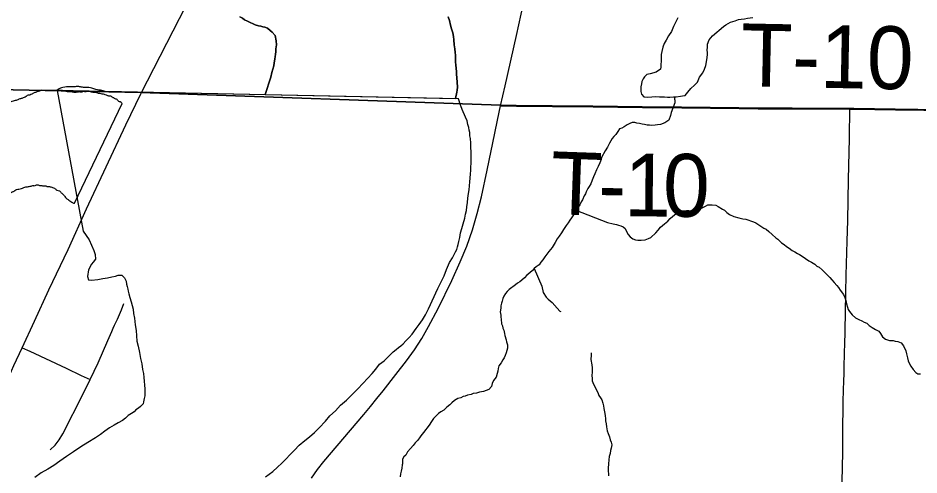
# Model space of a CAD drawing. Extents: x -483 to 680, y 0 to 440.
# Drawn here: x 111.22 to 151.99, y 110.14 to 130.81 of the extents above; entities that cross this region are included whole.
import ezdxf

# ---------------------------------------------------------------- set-up
doc = ezdxf.new("R2010")
doc.units = 0
for name, color, linetype in [('GM_X_County_Road', 7, 'Continuous'), ('GM_X_Major_River', 7, 'Continuous'), ('GM_X_Minor_Lake', 7, 'Continuous'), ('GM_X_Minor_River', 7, 'Continuous'), ('GM_X_State_Route', 7, 'Continuous'), ('GM_X_Township_Road', 7, 'Continuous'), ('GM_X_Township_Road_Text', 7, 'Continuous'), ('SH_Cut_Line', 7, 'Continuous')]:
    doc.layers.add(name, color=color, linetype=linetype)

msp = doc.modelspace()

# ---------------------------------------------------------------- linework, layer by layer
at = {"layer": 'GM_X_County_Road'}
for points in [[(133.061, 126.847), (133.259, 127.748), (133.774, 130.022), (134.2, 131.965)], [(124.501, 109.998), (124.772, 110.381), (125.061, 110.748), (125.664, 111.46), (126.869, 112.882), (127.164, 113.239), (127.456, 113.595), (127.746, 113.953), (128.32, 114.683), (128.794, 115.298), (129.156, 115.8), (129.491, 116.32), (129.802, 116.854), (130.234, 117.678), (130.851, 118.932), (131.235, 119.779), (131.524, 120.498), (131.78, 121.229), (132, 121.972), (132.191, 122.723), (132.454, 123.936), (132.804, 125.609), (132.925, 126.185), (133.061, 126.847)]]:
    msp.add_lwpolyline(points, dxfattribs=at)
at = {"layer": 'GM_X_Major_River'}
for p, q in [((113.154, 127.538), (112.286, 127.555)), ((131.149, 127.156), (112.985, 127.541)), ((122.408, 127.353), (131.016, 127.178)), ((113.77, 122.438), (115.939, 126.95))]:
    msp.add_line(p, q, dxfattribs=at)
for points in [[(121.264, 130.869), (121.376, 130.808), (121.469, 130.729), (121.6, 130.667), (121.732, 130.606), (121.863, 130.544), (121.957, 130.503), (122.108, 130.46), (122.202, 130.438), (122.297, 130.416), (122.391, 130.394), (122.504, 130.352), (122.634, 130.253), (122.727, 130.173), (122.855, 130.017), (122.905, 129.787), (122.918, 129.596), (122.893, 129.426), (122.889, 129.293), (122.866, 129.161), (122.863, 129.066), (122.84, 128.952), (122.816, 128.782), (122.792, 128.649), (122.749, 128.499), (122.706, 128.348), (122.662, 128.14), (122.408, 127.353)], [(122.408, 127.353), (122.662, 128.14), (122.706, 128.348), (122.749, 128.499), (122.792, 128.649), (122.816, 128.782), (122.84, 128.952), (122.863, 129.066), (122.866, 129.161), (122.889, 129.293), (122.893, 129.426), (122.918, 129.596), (122.905, 129.787), (122.855, 130.017), (122.727, 130.173), (122.634, 130.253), (122.504, 130.352), (122.391, 130.394), (122.297, 130.416), (122.202, 130.438), (122.108, 130.46), (121.957, 130.503), (121.863, 130.544), (121.732, 130.606), (121.6, 130.667), (121.469, 130.729), (121.376, 130.808), (121.264, 130.869)], [(131.016, 127.178), (131.076, 127.461), (131.098, 127.555), (131.102, 127.688), (131.078, 128.127), (131.063, 128.26), (131.067, 128.374), (131.053, 128.546), (131.039, 128.68), (131.024, 128.832), (131.011, 129.004), (131.015, 129.137), (131, 129.251), (130.986, 129.423), (130.954, 129.595), (130.942, 129.824), (130.928, 129.977), (130.895, 130.149), (130.844, 130.322), (130.792, 130.495), (130.742, 130.706), (130.689, 130.86)], [(130.689, 130.86), (130.742, 130.706), (130.792, 130.495), (130.844, 130.322), (130.895, 130.149), (130.928, 129.977), (130.942, 129.824), (130.954, 129.595), (130.986, 129.423), (131, 129.251), (131.015, 129.137), (131.011, 129.004), (131.024, 128.832), (131.039, 128.68), (131.053, 128.546), (131.067, 128.374), (131.063, 128.26), (131.078, 128.127), (131.102, 127.688), (131.098, 127.555), (131.076, 127.461), (131.016, 127.178)], [(112.985, 127.541), (114.173, 121.177), (114.306, 120.967), (114.438, 120.777), (114.647, 120.301), (114.704, 120.11), (114.722, 119.901), (114.627, 119.769)], [(131.018, 120.232), (131.075, 120.346), (131.113, 120.46), (131.133, 120.574), (131.171, 120.707), (131.209, 120.878), (131.247, 121.087), (131.305, 121.296), (131.362, 121.504), (131.439, 121.751), (131.477, 121.941), (131.516, 122.112), (131.535, 122.264), (131.554, 122.473), (131.574, 122.663), (131.612, 122.872), (131.631, 123.043), (131.651, 123.214), (131.67, 123.404), (131.689, 123.575), (131.69, 123.765), (131.709, 123.917), (131.709, 124.012), (131.709, 124.108), (131.729, 124.203), (131.729, 124.298), (131.729, 124.431), (131.729, 124.545), (131.73, 124.773), (131.711, 124.944), (131.711, 125.153), (131.693, 125.362), (131.674, 125.476), (131.674, 125.628), (131.636, 125.742), (131.617, 125.857), (131.58, 125.99), (131.542, 126.161), (131.466, 126.332), (131.315, 126.675), (131.258, 126.846), (131.239, 126.865), (131.149, 127.156)], [(122.424, 110.051), (122.747, 110.297), (122.957, 110.486), (123.166, 110.676), (123.357, 110.865), (123.528, 111.055), (123.738, 111.263), (123.947, 111.491), (124.195, 111.699), (124.404, 111.87), (124.633, 112.059), (124.843, 112.267), (125.128, 112.571), (125.338, 112.817), (125.585, 113.045), (125.814, 113.291), (126.081, 113.518), (126.347, 113.784), (126.595, 114.03), (126.824, 114.276), (127.052, 114.523), (127.243, 114.731), (127.414, 114.921), (127.586, 115.148), (127.795, 115.3), (127.929, 115.432), (128.043, 115.565), (128.195, 115.717), (128.329, 115.811), (128.443, 115.906), (128.538, 115.982), (128.652, 116.076), (128.767, 116.209), (128.919, 116.361), (129.052, 116.512), (129.243, 116.759), (129.377, 116.949), (129.529, 117.157), (129.663, 117.385), (129.796, 117.651), (130.216, 118.581), (130.369, 118.884), (130.502, 119.15), (130.617, 119.435), (130.751, 119.758), (130.884, 119.966), (130.96, 120.118), (131.018, 120.232)], [(114.627, 119.769), (114.551, 119.674), (114.417, 119.427), (114.359, 119.123), (114.416, 118.971), (114.549, 118.951), (114.834, 118.989), (115.063, 119.026), (115.272, 119.063), (115.462, 119.101), (115.633, 119.138), (115.748, 119.176), (115.919, 119.175), (116.033, 119.061), (116.108, 118.909), (116.127, 118.776), (116.165, 118.661), (116.184, 118.547), (116.203, 118.452), (116.24, 118.338), (116.278, 118.167), (116.335, 117.977), (116.392, 117.805), (116.429, 117.634), (116.448, 117.444), (116.486, 117.235), (116.523, 116.931), (116.561, 116.683), (116.579, 116.436), (116.598, 116.189), (116.654, 115.961), (116.711, 115.676), (116.767, 115.409), (116.824, 115.162), (116.861, 114.915), (116.899, 114.725), (116.918, 114.553), (116.955, 114.04), (116.955, 113.907), (116.955, 113.812), (116.954, 113.717), (116.935, 113.603), (116.897, 113.451), (116.878, 113.356), (116.763, 113.242), (116.668, 113.167), (116.554, 113.091), (116.478, 112.996), (116.363, 112.92), (116.211, 112.826), (116.078, 112.712), (115.945, 112.599), (115.754, 112.504), (115.564, 112.391), (115.355, 112.277), (115.145, 112.126), (114.955, 111.974), (114.726, 111.823), (114.384, 111.615), (114.06, 111.407), (113.736, 111.18), (113.413, 110.972), (113.108, 110.763), (112.842, 110.574), (112.575, 110.404), (112.27, 110.234), (111.985, 110.025)]]:
    msp.add_lwpolyline(points, dxfattribs=at)
for points in [[(112.286, 127.555), (112.166, 127.5), (112.109, 127.482), (112.013, 127.447), (111.955, 127.429), (111.897, 127.393), (111.84, 127.376), (111.762, 127.321), (111.686, 127.323), (111.59, 127.268), (111.398, 127.179), (111.34, 127.161), (111.264, 127.144), (111.206, 127.108), (111.053, 127.074), (110.938, 127.039), (110.842, 127.023), (110.785, 127.024), (110.69, 127.008), (110.576, 127.011), (110.518, 126.994), (110.442, 126.996), (110.385, 126.978), (110.024, 126.988), (109.948, 126.99), (109.796, 126.994), (109.721, 127.015), (109.664, 127.017), (109.551, 127.058), (109.494, 127.06), (109.381, 127.101), (109.306, 127.141), (109.23, 127.162), (109.174, 127.183), (109.118, 127.222), (109.061, 127.243), (109.004, 127.244), (108.93, 127.303), (108.854, 127.324), (108.797, 127.326), (108.684, 127.367), (108.61, 127.426), (108.556, 127.561), (108.558, 127.618), (108.549, 127.631)], [(115.939, 126.95), (115.841, 127.019), (115.785, 127.039), (115.729, 127.097), (115.673, 127.137), (115.617, 127.158), (115.561, 127.197), (115.504, 127.218), (115.448, 127.257), (115.392, 127.278), (115.335, 127.279), (115.278, 127.3), (115.165, 127.341), (115.09, 127.362), (115.033, 127.364), (114.92, 127.405), (114.863, 127.406), (114.787, 127.428), (114.655, 127.45), (114.579, 127.452), (114.503, 127.473), (114.238, 127.481), (114.162, 127.483), (114.104, 127.465), (113.971, 127.469), (113.914, 127.452), (113.686, 127.458), (113.61, 127.479), (113.42, 127.484), (113.364, 127.505), (113.288, 127.507), (113.231, 127.527), (113.174, 127.529), (113.154, 127.538)], [(105.121, 120.393), (105.198, 120.448), (105.256, 120.465), (105.333, 120.52), (105.41, 120.556), (105.468, 120.592), (105.545, 120.628), (105.738, 120.737), (105.91, 120.789), (106.257, 120.951), (106.392, 121.023), (106.507, 121.077), (106.585, 121.132), (106.642, 121.15), (106.738, 121.185), (106.796, 121.221), (106.891, 121.238), (107.025, 121.272), (107.141, 121.326), (107.237, 121.361), (107.352, 121.415), (107.544, 121.486), (107.679, 121.558), (107.776, 121.613), (107.89, 121.648), (108.18, 121.811), (108.295, 121.865), (108.391, 121.9), (108.506, 121.935), (108.583, 121.952), (108.697, 121.968), (108.774, 121.985), (108.869, 122.001), (108.983, 122.017), (109.041, 122.034), (109.117, 122.051), (109.251, 122.086), (109.329, 122.14), (109.425, 122.176), (109.482, 122.193), (109.56, 122.248), (109.675, 122.283), (109.734, 122.357), (109.849, 122.392), (109.983, 122.465), (110.117, 122.499), (110.233, 122.572), (110.349, 122.626), (110.406, 122.643), (110.484, 122.717), (110.599, 122.733), (110.792, 122.842), (110.965, 122.951), (111.023, 122.968), (111.081, 123.005), (111.158, 123.06), (111.254, 123.076), (111.484, 123.146), (111.58, 123.181), (111.656, 123.179), (111.732, 123.196), (111.809, 123.213), (111.885, 123.23), (111.942, 123.228), (112.057, 123.263), (112.133, 123.261), (112.189, 123.24), (112.303, 123.237), (112.36, 123.217), (112.474, 123.214), (112.53, 123.193), (112.644, 123.19), (112.701, 123.169), (112.87, 123.108), (112.982, 123.029), (113.095, 122.988), (113.151, 122.929), (113.207, 122.889), (113.318, 122.772), (113.373, 122.695), (113.428, 122.636), (113.484, 122.597), (113.652, 122.478), (113.765, 122.437), (113.77, 122.438)]]:
    msp.add_spline(points, degree=3, dxfattribs=at)
at = {"layer": 'GM_X_Minor_Lake'}
msp.add_lwpolyline([(141.086, 130.818), (141.006, 130.668), (140.945, 130.556), (140.883, 130.425), (140.8, 130.2), (140.661, 130.014), (140.559, 129.808), (140.459, 129.659), (140.397, 129.49), (140.352, 129.301), (140.329, 129.169), (140.325, 129.055), (140.322, 128.941), (140.319, 128.846), (140.315, 128.732), (140.311, 128.599), (140.289, 128.505), (140.094, 128.359), (139.825, 128.292), (139.672, 128.259), (139.573, 128.148), (139.513, 128.055), (139.452, 127.943), (139.429, 127.829), (139.406, 127.697), (139.399, 127.488), (139.434, 127.373), (139.544, 127.255), (139.715, 127.23), (139.906, 127.243), (140.077, 127.256), (140.249, 127.25), (140.382, 127.246), (140.477, 127.243), (140.61, 127.238), (140.724, 127.235), (140.877, 127.249), (141.01, 127.244), (141.202, 127.276), (141.297, 127.292), (141.412, 127.307), (141.531, 127.455), (141.67, 127.622), (141.827, 127.769), (141.965, 127.916), (142.067, 128.141), (142.206, 128.327), (142.288, 128.495), (142.351, 128.664), (142.375, 128.835), (142.4, 129.024), (142.423, 129.156), (142.426, 129.251), (142.411, 129.366), (142.415, 129.499), (142.419, 129.632), (142.502, 129.82), (142.641, 130.005), (143.15, 130.426), (143.247, 130.499), (143.461, 130.625), (143.672, 130.694), (143.826, 130.746), (143.941, 130.761), (144.094, 130.775), (144.228, 130.808), (144.477, 130.838)], dxfattribs=at)
msp.add_lwpolyline([(141.086, 130.818), (141.006, 130.668), (140.945, 130.556), (140.883, 130.425), (140.8, 130.2), (140.661, 130.014), (140.559, 129.808), (140.459, 129.659), (140.397, 129.49), (140.352, 129.301), (140.329, 129.169), (140.325, 129.055), (140.322, 128.941), (140.319, 128.846), (140.315, 128.732), (140.311, 128.599), (140.289, 128.505), (140.094, 128.359), (139.825, 128.292), (139.672, 128.259), (139.573, 128.148), (139.513, 128.055), (139.452, 127.943), (139.429, 127.829), (139.406, 127.697), (139.399, 127.488), (139.434, 127.373), (139.544, 127.255), (139.715, 127.23), (139.906, 127.243), (140.077, 127.256), (140.249, 127.25), (140.382, 127.246), (140.477, 127.243), (140.61, 127.238), (140.724, 127.235), (140.877, 127.249), (141.01, 127.244), (141.202, 127.276), (141.297, 127.292), (141.412, 127.307), (141.531, 127.455), (141.67, 127.622), (141.827, 127.769), (141.965, 127.916), (142.067, 128.141), (142.206, 128.327), (142.288, 128.495), (142.351, 128.664), (142.375, 128.835), (142.4, 129.024), (142.423, 129.156), (142.426, 129.251), (142.411, 129.366), (142.415, 129.499), (142.419, 129.632), (142.502, 129.82), (142.641, 130.005), (143.15, 130.426), (143.247, 130.499), (143.461, 130.625), (143.672, 130.694), (143.826, 130.746), (143.941, 130.761), (144.094, 130.775), (144.228, 130.808), (144.477, 130.838)], dxfattribs=at)
at = {"layer": 'GM_X_Minor_River'}
for points in [[(115.124, 127.498), (122.408, 127.353)], [(140.937, 126.976), (140.784, 126.532), (140.745, 126.399), (140.669, 126.19), (140.498, 126.077), (140.288, 126.001), (140.155, 125.983), (140.06, 125.964), (139.889, 125.945), (139.794, 125.965), (139.699, 125.965), (139.566, 126.003), (139.471, 126.004), (139.338, 126.042), (139.224, 126.061), (139.128, 126.081), (139.014, 126.081), (138.9, 126.044), (138.786, 125.987), (138.653, 125.892), (138.539, 125.835), (138.443, 125.798), (138.367, 125.684), (138.272, 125.551), (138.177, 125.456), (138.101, 125.362), (137.986, 125.153), (137.891, 124.963), (137.795, 124.811), (137.624, 124.508), (137.604, 124.413), (137.547, 124.261), (137.471, 124.09), (137.394, 123.938), (137.318, 123.767), (137.261, 123.634), (137.203, 123.483), (137.146, 123.312), (137.07, 123.198), (137.013, 123.103), (136.936, 122.951), (136.898, 122.856), (136.841, 122.761), (136.764, 122.59), (136.707, 122.496), (136.65, 122.363), (136.574, 122.249), (136.459, 122.116), (136.421, 122.002), (136.326, 121.87), (136.269, 121.775), (136.192, 121.661), (136.116, 121.547), (136.021, 121.433), (135.906, 121.244), (135.811, 121.092), (135.716, 120.94), (135.62, 120.826), (135.525, 120.656), (135.391, 120.428), (135.239, 120.257), (135.144, 120.124), (135.067, 120.011), (134.972, 119.878), (134.877, 119.764), (134.801, 119.65), (134.667, 119.556), (134.572, 119.48), (134.496, 119.385), (134.382, 119.29), (134.248, 119.177), (134.134, 119.063), (134.02, 118.949), (133.924, 118.874), (133.829, 118.817), (133.734, 118.741), (133.448, 118.533), (133.353, 118.438), (133.277, 118.343), (133.201, 118.23), (133.163, 118.116), (133.124, 118.002), (133.105, 117.907), (133.067, 117.793), (133.067, 117.679), (133.047, 117.527), (133.066, 117.375), (133.066, 117.28), (133.085, 117.184), (133.103, 116.975), (133.141, 116.88), (133.16, 116.785), (133.198, 116.69), (133.236, 116.538), (133.254, 116.443), (133.311, 116.252), (133.33, 116.157), (133.368, 116.024), (133.367, 115.872), (133.348, 115.777)], [(136.459, 122.116), (137.903, 121.561), (138.15, 121.503), (138.302, 121.464), (138.397, 121.445), (138.493, 121.407), (138.607, 121.368), (138.701, 121.292), (138.758, 121.159), (138.834, 121.026), (138.929, 120.911), (139.043, 120.816), (139.157, 120.778), (139.271, 120.758), (139.423, 120.758), (139.594, 120.776), (139.746, 120.833), (139.861, 120.889), (140.089, 121.098), (140.184, 121.211), (140.299, 121.344), (140.47, 121.496), (140.623, 121.628), (140.737, 121.742), (140.851, 121.856), (140.984, 121.95), (141.156, 122.045), (141.308, 122.083), (141.479, 122.101), (141.574, 122.101), (141.745, 122.081), (141.859, 122.081), (141.954, 122.1), (142.126, 122.194), (142.24, 122.251), (142.335, 122.308), (142.43, 122.364), (142.525, 122.364), (142.639, 122.364), (142.792, 122.344), (142.906, 122.287), (143.095, 122.172), (143.19, 122.115), (143.304, 122.019), (143.418, 121.924), (143.608, 121.828), (143.836, 121.771), (144.026, 121.732), (144.159, 121.713), (144.501, 121.598), (144.615, 121.54), (144.786, 121.426), (144.881, 121.368), (144.976, 121.311), (145.071, 121.254), (145.204, 121.158), (145.356, 121.025), (145.508, 120.872), (145.603, 120.815), (145.774, 120.643), (145.888, 120.567), (146.002, 120.472), (146.115, 120.395), (146.248, 120.3), (146.381, 120.242), (146.495, 120.166), (146.59, 120.109), (146.704, 120.032), (146.856, 119.937), (147.008, 119.822), (147.122, 119.765), (147.274, 119.67), (147.369, 119.593), (147.483, 119.536), (147.616, 119.421), (147.73, 119.307), (147.843, 119.193), (147.957, 119.078), (148.052, 118.964), (148.147, 118.849), (148.28, 118.716), (148.356, 118.621), (148.432, 118.506), (148.583, 118.297), (148.64, 118.164), (148.678, 118.031), (148.716, 117.878), (148.754, 117.726), (148.791, 117.631), (148.848, 117.536), (148.962, 117.383), (149.114, 117.25), (149.266, 117.173), (149.399, 117.116), (149.513, 117.059), (149.627, 117.001), (149.741, 116.906), (149.874, 116.81), (150.026, 116.715), (150.178, 116.639), (150.253, 116.543)], [(134.572, 119.48), (134.932, 118.681), (134.988, 118.395), (135.121, 118.186), (135.216, 118.09), (135.387, 117.938), (135.615, 117.69), (135.747, 117.556), (135.785, 117.537)], [(150.253, 116.543), (150.348, 116.391), (150.481, 116.276), (150.652, 116.219), (150.823, 116.218), (150.918, 116.199), (151.032, 116.18), (151.184, 116.122), (151.298, 115.989), (151.393, 115.761), (151.431, 115.627), (151.468, 115.437), (151.506, 115.304), (151.544, 115.19), (151.62, 115.056), (151.734, 114.904), (151.847, 114.771), (151.942, 114.713), (152.057, 114.713)], [(133.348, 115.777), (133.31, 115.663), (133.272, 115.549), (133.215, 115.435), (133.157, 115.341), (133.081, 115.208), (132.986, 115.075), (132.947, 114.961), (132.928, 114.828), (132.909, 114.733), (132.852, 114.562), (132.737, 114.41), (132.68, 114.278), (132.642, 114.145), (132.527, 114.012), (132.413, 113.955), (132.28, 113.918), (132.109, 113.88), (131.976, 113.842), (131.824, 113.824), (131.728, 113.786), (131.557, 113.749), (131.462, 113.711), (131.367, 113.692), (131.253, 113.636), (131.12, 113.598), (130.967, 113.503), (130.853, 113.409), (130.758, 113.314), (130.624, 113.2), (130.491, 113.068), (130.358, 112.992), (130.244, 112.916), (130.11, 112.784), (130.015, 112.689), (129.939, 112.556), (129.824, 112.385), (129.577, 112.063), (129.443, 111.911), (129.386, 111.817), (129.291, 111.703), (129.195, 111.589), (129.1, 111.475), (128.986, 111.343), (128.852, 111.191), (128.776, 111.039), (128.681, 110.963), (128.624, 110.849), (128.623, 110.716), (128.623, 110.64), (128.604, 110.602), (128.585, 110.45), (128.566, 110.317), (128.527, 110.185), (128.508, 110.051)], [(137.151, 115.671), (137.151, 115.633), (137.151, 115.556), (137.15, 115.366), (137.188, 115.119), (137.207, 114.986), (137.206, 114.796), (137.187, 114.644), (137.206, 114.511), (137.206, 114.397), (137.262, 114.245), (137.452, 113.864), (137.509, 113.731), (137.585, 113.635), (137.641, 113.54), (137.679, 113.388), (137.717, 113.274), (137.736, 113.141), (137.754, 112.989), (137.792, 112.836), (137.811, 112.684), (137.811, 112.589), (137.83, 112.456), (137.848, 112.323), (137.886, 112.133), (137.924, 112.019), (137.981, 111.867), (138.018, 111.733), (138.056, 111.619), (138.094, 111.505), (138.056, 111.353), (138.036, 111.239), (138.017, 111.106), (137.979, 110.973), (137.96, 110.821), (137.94, 110.65), (137.921, 110.441), (137.921, 110.308), (137.939, 110.194), (137.939, 110.099)]]:
    msp.add_lwpolyline(points, dxfattribs=at)
for points in [[(115.124, 127.498), (115.013, 127.533), (114.88, 127.556), (114.747, 127.578), (114.559, 127.64), (114.426, 127.663), (114.274, 127.667), (114.085, 127.691), (113.933, 127.714), (113.762, 127.7), (113.591, 127.705), (113.248, 127.676), (113.036, 127.586), (112.984, 127.542)], [(140.925, 127.247), (140.939, 127.043), (140.937, 126.976)]]:
    msp.add_spline(points, degree=3, dxfattribs=at)
at = {"layer": 'GM_X_State_Route'}
for points in [[(116.794, 127.421), (118.815, 131.35)], [(108.36, 109.527), (108.717, 110.22), (109.182, 111.204), (110.046, 113.03), (110.921, 114.85), (111.032, 115.088), (111.408, 115.896), (111.971, 117.103), (112.622, 118.514), (113.484, 120.341), (114.325, 122.178), (116.098, 125.979), (116.778, 127.387), (116.794, 127.421)]]:
    msp.add_lwpolyline(points, dxfattribs=at)
at = {"layer": 'GM_X_Township_Road'}
for points in [[(133.061, 126.847), (133.781, 126.832), (135.41, 126.815), (137.246, 126.796), (139.484, 126.772), (141.258, 126.754), (143.85, 126.726), (144.711, 126.708), (146.264, 126.705), (147.196, 126.7), (148.862, 126.687)], [(148.548, 111.821), (148.569, 113.647), (148.57, 113.802), (148.58, 114.106), (148.587, 114.256), (148.597, 114.404), (148.606, 114.711), (148.609, 114.868), (148.612, 115.181), (148.618, 115.49), (148.622, 115.641), (148.625, 115.795), (148.632, 115.948), (148.661, 117.471), (148.683, 118.398), (148.702, 119.174), (148.739, 120.717), (148.769, 121.646), (148.804, 123.508), (148.843, 125.369), (148.853, 125.83), (148.857, 126.289), (148.859, 126.444), (148.862, 126.687)], [(148.862, 126.687), (149.062, 126.686), (150.928, 126.662), (156.061, 126.593), (157.616, 126.554), (161.815, 126.504), (166.481, 126.44), (172.702, 126.362), (173.822, 126.344)], [(114.479, 114.46), (114.848, 115.22), (115.28, 116.22), (115.401, 116.5), (115.463, 116.635), (115.523, 116.777), (115.588, 116.913), (115.719, 117.189), (115.902, 117.609), (116.013, 117.895)], [(111.408, 115.896), (111.75, 115.736), (113.398, 114.967), (114.084, 114.645), (114.479, 114.46)], [(112.669, 111.27), (112.898, 111.483), (112.999, 111.602), (113.088, 111.731), (113.244, 112.001), (114.166, 113.813), (114.479, 114.46)], [(147.889, 76.411), (147.894, 76.698), (147.932, 79.493), (147.988, 83.064), (148.068, 87.721), (148.175, 94.087), (148.243, 97.191), (148.318, 100.762), (148.383, 103.4), (148.463, 106.504), (148.486, 108.523), (148.541, 111.162), (148.548, 111.821)]]:
    msp.add_lwpolyline(points, dxfattribs=at)
at = {"layer": 'SH_Cut_Line'}
for points in [[(156.049, 126.62), (150.917, 126.689), (149.05, 126.713), (148.85, 126.715), (147.185, 126.727), (146.252, 126.732), (144.7, 126.736), (143.839, 126.754), (141.246, 126.781), (139.472, 126.8), (137.235, 126.823), (135.398, 126.843), (133.769, 126.86), (133.049, 126.874), (116.783, 127.448), (74.201, 128.335)], [(74.201, 128.335), (116.783, 127.448), (133.049, 126.874), (133.769, 126.86), (135.398, 126.843), (137.235, 126.823), (139.472, 126.8), (141.246, 126.781), (143.839, 126.754), (144.7, 126.736), (146.252, 126.732), (147.185, 126.727), (148.85, 126.715), (149.05, 126.713), (150.917, 126.689), (156.049, 126.62)]]:
    msp.add_lwpolyline(points, dxfattribs=at)

# ---------------------------------------------------------------- texts
at = {"layer": 'GM_X_Township_Road_Text'}
for s, height, rotation, p in [('T-10', 2.8409, 358.865, (143.91, 127.732)), ('T', 2.841, 357.9853, (135.276, 121.945)), ('1', 2.841, 359.3962, (138.643, 121.849)), ('0', 2.841, 359.5163, (140.399, 121.831)), ('-', 2.841, 359.0325, (137.457, 121.869))]:
    msp.add_text(s, height=height, rotation=rotation, dxfattribs=at).set_placement(p)

doc.saveas('drawing.dxf')
